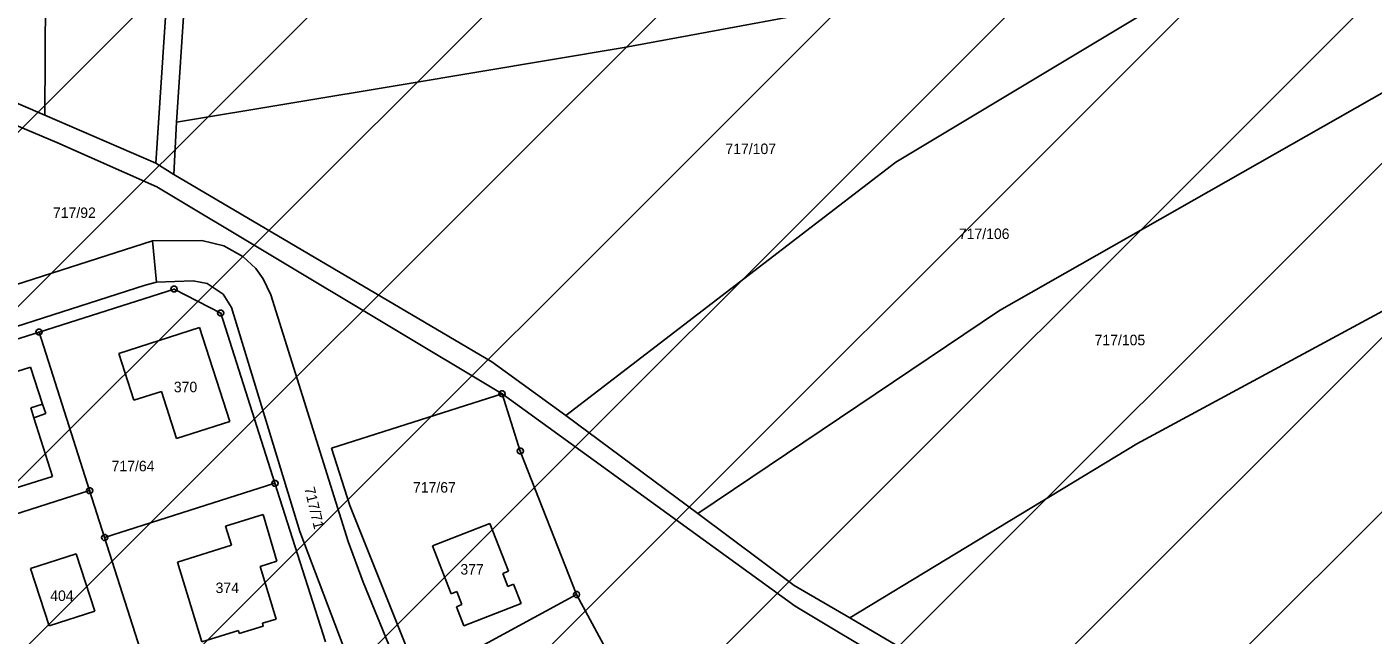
# Model space of a CAD drawing. Extents: x -593358 to -590116, y -1072518 to -1068420.
# Drawn here: x -591378.7 to -591160.3, y -1070234.1 to -1070135.4 of the extents above; entities that cross this region are included whole.
import ezdxf

# ---------------------------------------------------------------- set-up
doc = ezdxf.new("R2010")
doc.units = 0
for name, color, linetype in [('Parcela KN', 7, 'Continuous'), ('Parcela ZE', 7, 'Continuous'), ('Parcelní číslo', 7, 'Continuous'), ('Parcelní číslo_stavební', 7, 'Continuous'), ('stavby - vnitřní kresba', 7, 'Continuous'), ('Vrstva 24', 7, 'Continuous'), ('zastavitelné území', 7, 'Continuous')]:
    doc.layers.add(name, color=color, linetype=linetype)

msp = doc.modelspace()

# ---------------------------------------------------------------- linework, layer by layer
at = {"layer": 'Parcela KN'}
for p, q in [((-591399, -1070143.63), (-591373.89, -1070154.22)), ((-591373.89, -1070154.22), (-591357.66, -1070161.41)), ((-591357.66, -1070161.41), (-591301.65, -1070194.98)), ((-591358.35, -1070170.17), (-591401.29, -1070183.92)), ((-591358.35, -1070170.17), (-591350.34, -1070170.12)), ((-591357.72, -1070176.88), (-591358.35, -1070170.17)), ((-591350.34, -1070170.12), (-591346.78, -1070170.98)), ((-591346.78, -1070170.98), (-591343.72, -1070172.68)), ((-591343.72, -1070172.68), (-591341.61, -1070174.66)), ((-591341.61, -1070174.66), (-591340.4, -1070176.35)), ((-591340.4, -1070176.35), (-591339.14, -1070178.94)), ((-591397.42, -1070189.49), (-591359.52, -1070177.34)), ((-591354.84, -1070177.99), (-591376.75, -1070184.98)), ((-591359.52, -1070177.34), (-591357.72, -1070176.88)), ((-591351.74, -1070176.65), (-591357.72, -1070176.88)), ((-591347.29, -1070181.88), (-591354.84, -1070177.99)), ((-591349.46, -1070177.09), (-591351.74, -1070176.65)), ((-591346.89, -1070178.8), (-591349.46, -1070177.09)), ((-591345.51, -1070180.98), (-591346.89, -1070178.8)), ((-591339.14, -1070178.94), (-591326.6, -1070218.97)), ((-591338.49, -1070209.51), (-591347.29, -1070181.88)), ((-591339.16, -1070201.94), (-591345.51, -1070180.98)), ((-591376.75, -1070184.98), (-591398.66, -1070191.96)), ((-591368.55, -1070210.7), (-591376.75, -1070184.98)), ((-591363.82, -1070188.47), (-591350.71, -1070184.21)), ((-591350.71, -1070184.21), (-591345.82, -1070199.5)), ((-591361.36, -1070196.03), (-591363.82, -1070188.47)), ((-591393.76, -1070195.61), (-591378.12, -1070190.66)), ((-591378.12, -1070190.66), (-591376.19, -1070196.68)), ((-591356.88, -1070194.6), (-591361.36, -1070196.03)), ((-591354.44, -1070202.26), (-591356.88, -1070194.6)), ((-591329.29, -1070203.79), (-591301.65, -1070194.98)), ((-591301.65, -1070194.98), (-591298.68, -1070204.29)), ((-591375.67, -1070198.18), (-591377.59, -1070198.87)), ((-591376.19, -1070196.68), (-591375.67, -1070198.18)), ((-591377.59, -1070198.87), (-591374.57, -1070208.41)), ((-591345.82, -1070199.5), (-591354.44, -1070202.26)), ((-591334.44, -1070217.32), (-591339.16, -1070201.94)), ((-591326.32, -1070213.12), (-591329.29, -1070203.79)), ((-591298.68, -1070204.29), (-591289.56, -1070227.57)), ((-591374.57, -1070208.41), (-591382.34, -1070210.86)), ((-591396.18, -1070219.51), (-591368.55, -1070210.7)), ((-591368.55, -1070210.7), (-591366.12, -1070218.32)), ((-591366.12, -1070218.32), (-591338.49, -1070209.51)), ((-591330.29, -1070235.24), (-591338.49, -1070209.51)), ((-591315.03, -1070241.37), (-591326.32, -1070213.12)), ((-591346.48, -1070216.48), (-591340.42, -1070214.58)), ((-591340.42, -1070214.58), (-591338.19, -1070222.17)), ((-591345.51, -1070219.56), (-591346.48, -1070216.48)), ((-591327.42, -1070235.87), (-591334.44, -1070217.32)), ((-591303.63, -1070216.03), (-591312.92, -1070219.66)), ((-591300.6, -1070223.78), (-591303.63, -1070216.03)), ((-591366.12, -1070218.32), (-591360.35, -1070236.42)), ((-591354.32, -1070222.32), (-591345.51, -1070219.56)), ((-591326.6, -1070218.97), (-591324.18, -1070225.55)), ((-591312.92, -1070219.66), (-591309.89, -1070227.42)), ((-591370.71, -1070220.94), (-591378.14, -1070223.34)), ((-591367.72, -1070230.28), (-591370.71, -1070220.94)), ((-591338.19, -1070222.17), (-591340.88, -1070223.03)), ((-591378.14, -1070223.34), (-591375.09, -1070232.65)), ((-591350.36, -1070235.25), (-591354.32, -1070222.32)), ((-591340.88, -1070223.03), (-591338.28, -1070231.58)), ((-591301.53, -1070224.14), (-591300.6, -1070223.78)), ((-591300.72, -1070226.23), (-591301.53, -1070224.14)), ((-591324.18, -1070225.55), (-591319.54, -1070236.9)), ((-591299.79, -1070225.86), (-591300.72, -1070226.23)), ((-591298.55, -1070229.02), (-591299.79, -1070225.86)), ((-591289.56, -1070227.57), (-591315.03, -1070241.37)), ((-591309.89, -1070227.42), (-591308.97, -1070227.07)), ((-591308.97, -1070227.07), (-591308.18, -1070229.15)), ((-591276.69, -1070251.33), (-591289.56, -1070227.57)), ((-591375.09, -1070232.65), (-591367.72, -1070230.28)), ((-591308.18, -1070229.15), (-591309.06, -1070229.54)), ((-591309.06, -1070229.54), (-591307.83, -1070232.65)), ((-591307.83, -1070232.65), (-591298.55, -1070229.02)), ((-591340.37, -1070232.69), (-591344.28, -1070233.87)), ((-591338.28, -1070231.58), (-591340.51, -1070232.22)), ((-591340.51, -1070232.22), (-591340.37, -1070232.69)), ((-591344.42, -1070233.41), (-591350.36, -1070235.25)), ((-591344.28, -1070233.87), (-591344.42, -1070233.41))]:
    msp.add_line(p, q, dxfattribs=at)
at = {"layer": 'Parcela ZE'}
for p, q in [((-591375.8, -1070149.77), (-591375.62, -1070111.37)), ((-591355.15, -1070117.2), (-591357.82, -1070157.55)), ((-591354.44, -1070150.92), (-591352.9, -1070127.69)), ((-591281.83, -1070138.77), (-591230.77, -1070129.32)), ((-591237.74, -1070157.37), (-591197.5, -1070133.22)), ((-591317.69, -1070144.77), (-591281.83, -1070138.77)), ((-591375.8, -1070149.77), (-591394.33, -1070141.82)), ((-591220.95, -1070181.47), (-591151.17, -1070141.76)), ((-591354.44, -1070150.92), (-591317.69, -1070144.77)), ((-591357.82, -1070157.55), (-591375.8, -1070149.77)), ((-591354.91, -1070159.41), (-591354.44, -1070150.92)), ((-591354.91, -1070159.41), (-591357.82, -1070157.55)), ((-591291.28, -1070198.51), (-591237.74, -1070157.37)), ((-591303.32, -1070189.77), (-591354.91, -1070159.41)), ((-591198.68, -1070203.12), (-591142.2, -1070172.57)), ((-591269.88, -1070214.43), (-591220.95, -1070181.47)), ((-591291.28, -1070198.51), (-591303.32, -1070189.77)), ((-591301.65, -1070194.98), (-591254.08, -1070229.47)), ((-591269.88, -1070214.43), (-591291.28, -1070198.51)), ((-591245.21, -1070231.36), (-591198.68, -1070203.12)), ((-591254.25, -1070226.07), (-591269.88, -1070214.43)), ((-591245.21, -1070231.36), (-591254.25, -1070226.07)), ((-591254.08, -1070229.47), (-591213.05, -1070253.96)), ((-591219.67, -1070246.32), (-591245.21, -1070231.36))]:
    msp.add_line(p, q, dxfattribs=at)
at = {"layer": 'stavby - vnitřní kresba'}
for p, q in [((-591378.09, -1070197.28), (-591376.19, -1070196.68)), ((-591377.59, -1070198.87), (-591378.09, -1070197.28))]:
    msp.add_line(p, q, dxfattribs=at)
at = {"layer": 'Vrstva 24'}
for p, q in [((-591354.96, -1070177.99), (-591354.72, -1070177.99)), ((-591347.41, -1070181.88), (-591347.17, -1070181.88)), ((-591376.87, -1070184.98), (-591376.63, -1070184.98)), ((-591301.77, -1070194.98), (-591301.53, -1070194.98)), ((-591298.8, -1070204.29), (-591298.56, -1070204.29)), ((-591368.67, -1070210.7), (-591368.43, -1070210.7)), ((-591338.61, -1070209.51), (-591338.37, -1070209.51)), ((-591366.24, -1070218.32), (-591366, -1070218.32)), ((-591289.68, -1070227.57), (-591289.44, -1070227.57))]:
    msp.add_line(p, q, dxfattribs=at)
for points in [[(-591354.69, -1070177.51), (-591354.44, -1070177.69), (-591354.34, -1070177.98), (-591354.44, -1070178.27), (-591354.69, -1070178.45), (-591355, -1070178.45), (-591355.25, -1070178.27), (-591355.35, -1070177.98), (-591355.25, -1070177.69), (-591355, -1070177.51)], [(-591347.14, -1070181.4), (-591346.89, -1070181.58), (-591346.79, -1070181.87), (-591346.89, -1070182.16), (-591347.14, -1070182.34), (-591347.45, -1070182.34), (-591347.7, -1070182.16), (-591347.8, -1070181.87), (-591347.7, -1070181.58), (-591347.45, -1070181.4)], [(-591376.6, -1070184.5), (-591376.35, -1070184.68), (-591376.25, -1070184.97), (-591376.35, -1070185.26), (-591376.6, -1070185.44), (-591376.91, -1070185.44), (-591377.16, -1070185.26), (-591377.26, -1070184.97), (-591377.16, -1070184.68), (-591376.91, -1070184.5)], [(-591301.5, -1070194.5), (-591301.25, -1070194.68), (-591301.15, -1070194.97), (-591301.25, -1070195.26), (-591301.5, -1070195.44), (-591301.81, -1070195.44), (-591302.06, -1070195.26), (-591302.16, -1070194.97), (-591302.06, -1070194.68), (-591301.81, -1070194.5)], [(-591298.53, -1070203.81), (-591298.28, -1070203.99), (-591298.18, -1070204.28), (-591298.28, -1070204.57), (-591298.53, -1070204.75), (-591298.84, -1070204.75), (-591299.09, -1070204.57), (-591299.19, -1070204.28), (-591299.09, -1070203.99), (-591298.84, -1070203.81)], [(-591338.34, -1070209.03), (-591338.09, -1070209.21), (-591337.99, -1070209.5), (-591338.09, -1070209.79), (-591338.34, -1070209.97), (-591338.65, -1070209.97), (-591338.9, -1070209.79), (-591339, -1070209.5), (-591338.9, -1070209.21), (-591338.65, -1070209.03)], [(-591368.4, -1070210.22), (-591368.15, -1070210.4), (-591368.05, -1070210.69), (-591368.15, -1070210.98), (-591368.4, -1070211.16), (-591368.71, -1070211.16), (-591368.96, -1070210.98), (-591369.06, -1070210.69), (-591368.96, -1070210.4), (-591368.71, -1070210.22)], [(-591365.97, -1070217.84), (-591365.72, -1070218.02), (-591365.62, -1070218.31), (-591365.72, -1070218.6), (-591365.97, -1070218.78), (-591366.28, -1070218.78), (-591366.53, -1070218.6), (-591366.63, -1070218.31), (-591366.53, -1070218.02), (-591366.28, -1070217.84)], [(-591289.41, -1070227.09), (-591289.16, -1070227.27), (-591289.06, -1070227.56), (-591289.16, -1070227.85), (-591289.41, -1070228.03), (-591289.72, -1070228.03), (-591289.97, -1070227.85), (-591290.07, -1070227.56), (-591289.97, -1070227.27), (-591289.72, -1070227.09)]]:
    msp.add_lwpolyline(points, close=True, dxfattribs=at)
at = {"layer": 'zastavitelné území'}
for p, q in [((-591530.725, -1070303.099), (-591218.628, -1069991.002)), ((-591530.106, -1070330.765), (-591209.771, -1070010.429)), ((-591520.522, -1070349.464), (-591200.819, -1070029.761)), ((-591509.234, -1070366.46), (-591191.409, -1070048.635)), ((-591511.223, -1070396.734), (-591184.75, -1070070.261)), ((-591535.698, -1070449.493), (-591179.315, -1070093.111)), ((-591513.288, -1070455.368), (-591170.017, -1070112.097)), ((-591467.818, -1070438.181), (-591160.472, -1070130.836)), ((-591375.97, -1070374.618), (-591146.829, -1070145.477)), ((-591336.028, -1070362.96), (-591136.942, -1070163.875)), ((-591306.703, -1070361.92), (-591132.384, -1070187.601))]:
    msp.add_line(p, q, dxfattribs=at)

# ---------------------------------------------------------------- texts
at = {"layer": 'Parcelní číslo'}
for s, p in [('717/107', (-591265.412, -1070156.08)), ('717/92', (-591374.498, -1070166.45)), ('717/106', (-591227.542, -1070169.87)), ('717/105', (-591205.529, -1070187.11)), ('717/64', (-591364.984, -1070207.56)), ('717/67', (-591316.094, -1070211.02))]:
    msp.add_text(s, height=1.7, dxfattribs=at).set_placement(p)
msp.add_text('717/71', height=1.7, rotation=283.67141, dxfattribs=at).set_placement((-591333.741, -1070210.318))
at = {"layer": 'Parcelní číslo_stavební'}
for s, p in [('370', (-591354.888, -1070194.73)), ('377', (-591308.401, -1070224.32)), ('374', (-591348.111, -1070227.32)), ('404', (-591374.941, -1070228.6))]:
    msp.add_text(s, height=1.7, dxfattribs=at).set_placement(p)

doc.saveas('drawing.dxf')
